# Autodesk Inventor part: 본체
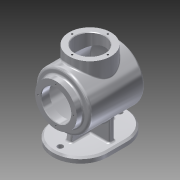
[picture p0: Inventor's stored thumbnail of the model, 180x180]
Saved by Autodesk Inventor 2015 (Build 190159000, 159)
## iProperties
Created: 2016-04
Part Number: 본체
Material: 알루미늄 6061
Document SubType Name: Modeling
Designer: Administrator
Density: 2.7 g/cm^3
Appearance: 알루미늄 - 평지
Mass: 906.174 g
Surface Area: 1226.76 cm^2
Volume: 335.62 cm^3
Author: Administrator
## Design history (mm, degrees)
sketch "스케치1"
  geometry: C1 r 50 at (0, 0); 1 further point
  constraints: 1 centre point, 1 coincident
  dimensions: "d0" = 100 diameter of C1
extrude "돌출1" new body sketch "스케치1" distance "d1" = 110; taper "d2" = 0 deg
sketch "스케치2"
  geometry: L1 (50, 110)-(-50, 110) reference; L2 (0, 135.081)-(0, -24.55); L3 (145.081, -10)-(120, -10); A1 r 120 centre (0, -10) between (120, -10) and (0, 110); A2 r 145.081 centre (0, -10) between (145.081, -10) and (0, 135.081); 1 further point
  constraints: 4 end point, 4 point on circle, 2 centre point, 1 coincident, 1 horizontal, 1 point on line, 1 tangent, 1 vertical
  dimensions: "d3" = 120 radius of A1
revolve "회전1" sketch "스케치2" stored, may be unused: angle "d4" = 90 deg
sketch "스케치3"
  geometry: C1 r 50 at (0, 0) reference
node "작업 평면1"
sketch "스케치5"
  geometry: L1 (-50, 0)-(50, 0) reference; C1 r 38 at (0, 50); 1 further point
  constraints: 1 centre point
  dimensions: "d6" = 76 diameter of C1
extrude "돌출2" join sketch "스케치5" distance "d7" = 40; taper "d8" = 0 deg
sketch "스케치7"
  geometry: L1 (50, 0)-(50, 99.087) reference; L2 (-50, 0)-(-50, 99.087) reference; L3 (47, 3)-(47, 97.145); L4 (47, 3)-(0, 3); L5 (0, 3)-(0, 107); A1 r 120 centre (0, -10) between (50, 99.087) and (-50, 99.087) reference; A2 r 117 centre (0, -10) between (47, 97.145) and (0, 107); 1 further point
  constraints: 6 end point, 2 point on circle, 1 centre point
revolve "회전2" sketch "스케치7" stored, may be unused: angle "d10" = 90 deg
sketch "스케치8"
  geometry: C1 r 38 at (0, 0) reference; C2 r 27 at (0, 0); 5 further points
  constraints: 1 centre point, 1 coincident
  dimensions: "d11" = 54 diameter of C2
extrude "돌출3" cut sketch "스케치8" distance "d13" = 40; taper "d14" = 0 deg
sketch "스케치9"
  geometry: 5 further points
hole "구멍1" sketch "스케치9" at (32.5, 0), (0, 32.5), (-32.5, 0), (0, -32.5) diameter "d16" = 3.242; stored, may be unused: countersink angle "d20" = 90 deg, drill point angle "d22" = 118 deg; dims "d17" = 8, "d18" = 4, "d19" = 2, "d21" = 10
sketch "스케치10"
  geometry: C1 r 50 at (0, 0) reference; C2 r 38 at (0, 0)
  constraints: 1 centre point, 1 coincident
  dimensions: "d23" = 76 diameter of C2
extrude "돌출4" join sketch "스케치10" distance "d24" = 12; taper "d25" = 0 deg
sketch "스케치11"
  geometry: C1 r 38 at (0, 0) reference; C2 r 27 at (0, 0)
  constraints: 1 centre point, 1 coincident
  dimensions: "d26" = 54 diameter of C2
extrude "돌출5" cut sketch "스케치11" distance "d27" = 15; taper "d28" = 0 deg
sketch "스케치12"
  geometry: 4 further points
hole "구멍2" sketch "스케치12" at (0, 32.5), (-32.5, 0), (0, -32.5), (32.5, 0) diameter "d30" = 3.242; stored, may be unused: countersink angle "d34" = 90 deg, drill point angle "d36" = 118 deg; dims "d31" = 8, "d32" = 4, "d33" = 2, "d35" = 10
node "작업 평면2"
sketch "스케치13"
  geometry: L1 (0, 117.5)-(0, 117.5); L2 (50, 67.5)-(50, 32.5); L3 (0, -17.5)-(0, -17.5); L4 (-50, 32.5)-(-50, 67.5); L5 (-50, 117.5)-(50, -17.5); L6 (50, 117.5)-(-50, -17.5); A1 r 50 centre (0, 32.5) between (-50, 32.5) and (0, -17.5); A2 r 50 centre (0, 32.5) between (0, -17.5) and (50, 32.5); A3 r 50 centre (0, 67.5) between (50, 67.5) and (0, 117.5); A4 r 50 centre (0, 67.5) between (0, 117.5) and (-50, 67.5); 2 further points
  constraints: 12 end point, 8 point on circle, 8 point on line, 8 tangent, 4 centre point, 3 equal radius, 2 midpoint, 2 parallel, 1 horizontal, 1 perpendicular
  dimensions: "d38" = 100 distance of L5.end L6.end; "d39" = 135 distance of L6.start L5.end; "d40" = 50 radius of A1
extrude "돌출6" join sketch "스케치13" distance "d41" = 10; taper "d42" = 0 deg
sketch "스케치17"
  geometry: L1 (65, 51.621)-(65, 48.379) reference; L2 (-69, 10)-(-69, 50); L3 (-69, 10)-(-48.488, 13.617); L4 (-69, 10)-(-48.171, 10); L5 (-48.488, 13.617)-(-48.488, 50); L6 (-69, 90)-(-69, 50); L7 (-69, 90)-(-48.488, 86.383); L8 (-69, 90)-(-48.171, 90); L9 (-48.488, 86.383)-(-48.488, 50); 1 further point
  constraints: 16 end point, 1 equal length, 1 horizontal
  dimensions: "d54" = 10 deg angle of L4 L3
extrude "돌출11" join sketch "스케치17" stored distance "d55" = 10; taper "d56" = 0 deg
sketch "스케치18"
  geometry: L1 (-40, -55)-(40, -55); L2 (40, -55)-(40, -45); L3 (40, -45)-(-40, -45); L4 (-40, -45)-(-40, -55); L5 (-40, -55)-(40, -45); L6 (40, -55)-(-40, -45); C1 r 38 at (0, -50) reference; 2 further points
  constraints: 12 end point, 2 midpoint, 2 parallel, 1 horizontal, 1 perpendicular
  dimensions: "d57" = 10 distance of L2.end L1.end; "d79" = 0 distance of C1.centre point (0, -50)
extrude "돌출12" join sketch "스케치18" stored distance "d58" = 10; taper "d59" = 0 deg
sketch "스케치19"
  geometry: L1 (0, -50)-(20.245, -50); C1 r 38 at (0, -50) reference; C2 r 5 at (0, 4); C3 r 5 at (0, -104); 1 further point
  constraints: 2 centre point, 2 end point, 1 horizontal
  dimensions: "d60" = 10 diameter of C2; "d61" = 10 diameter of C3
extrude "돌출13" cut sketch "스케치19" distance "d62" = 10; taper "d63" = 0 deg
fillet "모깎기2" dims "d64" = 5
fillet "모깎기3" dims "d65" = 2
fillet "모깎기4" dims "d66" = 3
fillet "모깎기5" dims "d67" = 3
fillet "모깎기6" dims "d68" = 3
chamfer "모따기1" distance "d69" = 3; stored, may be unused: second distance "d70" = 2, angle "d71" = 45 deg
chamfer "모따기2" distance "d72" = 1; stored, may be unused: second distance "d73" = 2, angle "d74" = 45 deg
node "작업 평면3"
sketch "스케치20"
  geometry: 3 further points
  constraints: 1 coincident, 3 other
  dimensions: "d75" = 0 distance of point (0, 0) point (0, 0); "d76" = 0 distance of point (0, 0) point (0, 0)
feature "엠보싱1" sketch "스케치20" dims "d77" = 0.5, "d78" = 0
node "솔리드1"
other parameters: "d5" = 65, "d37" = -79
